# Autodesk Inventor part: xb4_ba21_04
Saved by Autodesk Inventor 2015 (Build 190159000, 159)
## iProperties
Created: 2018-04
Part Number: xb4_ba21_04
Checked By: TraceParts S.A.
Material: Generic
Catalog Web Link: www.traceparts.com
Document SubType Name: Modeling
Designer: TraceParts
Density: 1 g/cm^3
Appearance: Default
Company: TraceParts S.A.
Author: TraceParts
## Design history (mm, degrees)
feature "xb4_ba21_04.ipt"
body "Solid1"
